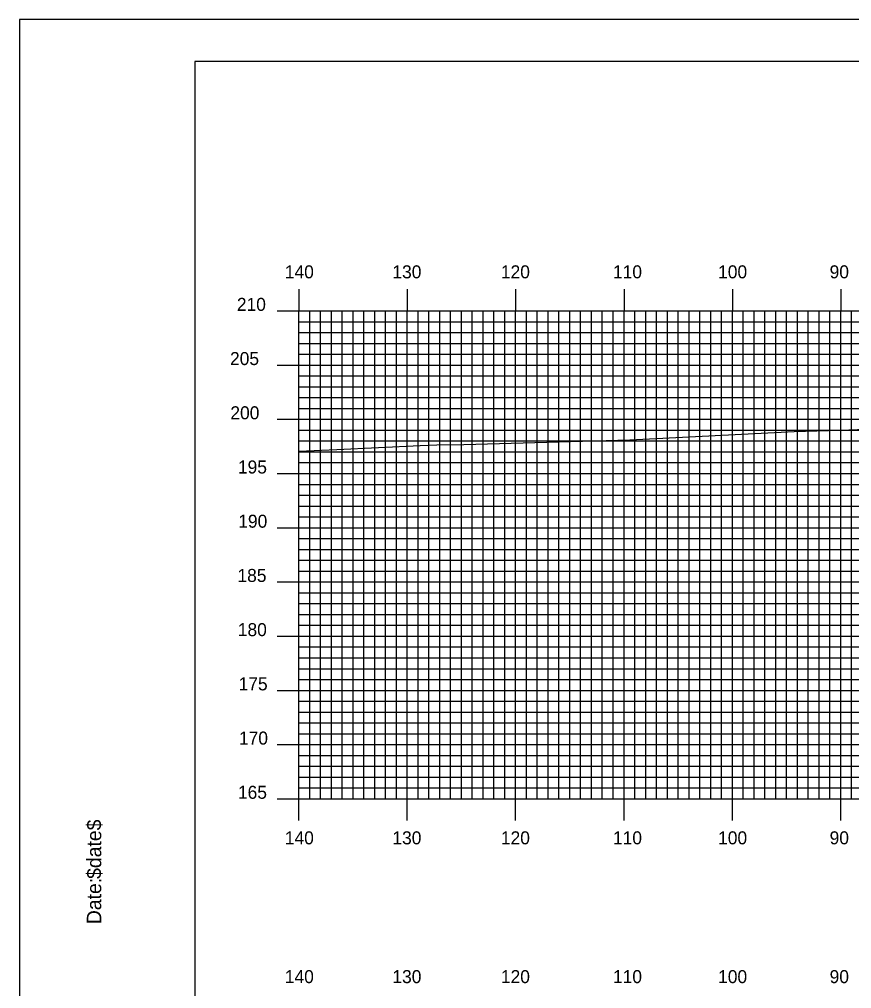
# Model space of a CAD drawing. Extents: x 1795633 to 1795976, y 442591 to 442811.
# Drawn here: x 1795633.1 to 1795709.9, y 442721.2 to 442810.5 of the extents above; entities that cross this region are included whole.
import ezdxf

# ---------------------------------------------------------------- set-up
doc = ezdxf.new("R2010")
doc.units = 0
for name, color, linetype in [('BORDER', 7, 'Continuous'), ('H_V ANNOTATION', 7, 'Continuous'), ('MAJOR', 7, 'Continuous'), ('MINOR', 7, 'Continuous'), ('PLOT BOUNDARY', 7, 'Continuous'), ('S_Roadway_Centerline', 7, 'Continuous')]:
    doc.layers.add(name, color=color, linetype=linetype)

msp = doc.modelspace()

# ---------------------------------------------------------------- linework, layer by layer
at = {"layer": 'BORDER'}
msp.add_lwpolyline([(1795649.279, 442596.665), (1795969.279, 442596.665), (1795969.279, 442806.665), (1795649.279, 442806.665)], close=True, dxfattribs=at)
at = {"layer": 'MAJOR'}
for p, q in [((1795658.879, 442785.669), (1795658.879, 442783.665)), ((1795668.879, 442785.669), (1795668.879, 442783.665)), ((1795678.879, 442785.669), (1795678.879, 442783.665)), ((1795688.879, 442785.669), (1795688.879, 442783.665)), ((1795698.879, 442785.669), (1795698.879, 442783.665)), ((1795708.879, 442785.669), (1795708.879, 442783.665)), ((1795656.875, 442783.665), (1795658.879, 442783.665)), ((1795658.879, 442783.665), (1795938.879, 442783.665)), ((1795658.879, 442738.665), (1795658.879, 442783.665)), ((1795658.879, 442738.665), (1795658.879, 442783.665)), ((1795658.879, 442783.665), (1795938.879, 442783.665)), ((1795668.879, 442738.665), (1795668.879, 442783.665)), ((1795678.879, 442738.665), (1795678.879, 442783.665)), ((1795688.879, 442738.665), (1795688.879, 442783.665)), ((1795698.879, 442738.665), (1795698.879, 442783.665)), ((1795708.879, 442738.665), (1795708.879, 442783.665)), ((1795656.875, 442778.665), (1795658.879, 442778.665)), ((1795658.879, 442778.665), (1795938.879, 442778.665)), ((1795656.875, 442773.665), (1795658.879, 442773.665)), ((1795658.879, 442773.665), (1795938.879, 442773.665)), ((1795656.875, 442768.665), (1795658.879, 442768.665)), ((1795658.879, 442768.665), (1795938.879, 442768.665)), ((1795656.875, 442763.665), (1795658.879, 442763.665)), ((1795658.879, 442763.665), (1795938.879, 442763.665)), ((1795656.875, 442758.665), (1795658.879, 442758.665)), ((1795658.879, 442758.665), (1795938.879, 442758.665)), ((1795656.875, 442753.665), (1795658.879, 442753.665)), ((1795658.879, 442753.665), (1795938.879, 442753.665)), ((1795656.875, 442748.665), (1795658.879, 442748.665)), ((1795658.879, 442748.665), (1795938.879, 442748.665)), ((1795656.875, 442743.665), (1795658.879, 442743.665)), ((1795658.879, 442743.665), (1795938.879, 442743.665)), ((1795656.875, 442738.665), (1795658.879, 442738.665)), ((1795658.879, 442738.665), (1795938.879, 442738.665)), ((1795658.879, 442738.665), (1795938.879, 442738.665)), ((1795658.879, 442736.661), (1795658.879, 442738.665)), ((1795668.879, 442736.661), (1795668.879, 442738.665)), ((1795678.879, 442736.661), (1795678.879, 442738.665)), ((1795688.879, 442736.661), (1795688.879, 442738.665)), ((1795698.879, 442736.661), (1795698.879, 442738.665)), ((1795708.879, 442736.661), (1795708.879, 442738.665))]:
    msp.add_line(p, q, dxfattribs=at)
at = {"layer": 'MINOR'}
for p, q in [((1795659.879, 442738.665), (1795659.879, 442783.665)), ((1795660.879, 442738.665), (1795660.879, 442783.665)), ((1795661.879, 442738.665), (1795661.879, 442783.665)), ((1795662.879, 442738.665), (1795662.879, 442783.665)), ((1795663.879, 442738.665), (1795663.879, 442783.665)), ((1795664.879, 442738.665), (1795664.879, 442783.665)), ((1795665.879, 442738.665), (1795665.879, 442783.665)), ((1795666.879, 442738.665), (1795666.879, 442783.665)), ((1795667.879, 442738.665), (1795667.879, 442783.665)), ((1795669.879, 442738.665), (1795669.879, 442783.665)), ((1795670.879, 442738.665), (1795670.879, 442783.665)), ((1795671.879, 442738.665), (1795671.879, 442783.665)), ((1795672.879, 442738.665), (1795672.879, 442783.665)), ((1795673.879, 442738.665), (1795673.879, 442783.665)), ((1795674.879, 442738.665), (1795674.879, 442783.665)), ((1795675.879, 442738.665), (1795675.879, 442783.665)), ((1795676.879, 442738.665), (1795676.879, 442783.665)), ((1795677.879, 442738.665), (1795677.879, 442783.665)), ((1795679.879, 442738.665), (1795679.879, 442783.665)), ((1795680.879, 442738.665), (1795680.879, 442783.665)), ((1795681.879, 442738.665), (1795681.879, 442783.665)), ((1795682.879, 442738.665), (1795682.879, 442783.665)), ((1795683.879, 442738.665), (1795683.879, 442783.665)), ((1795684.879, 442738.665), (1795684.879, 442783.665)), ((1795685.879, 442738.665), (1795685.879, 442783.665)), ((1795686.879, 442738.665), (1795686.879, 442783.665)), ((1795687.879, 442738.665), (1795687.879, 442783.665)), ((1795689.879, 442738.665), (1795689.879, 442783.665)), ((1795690.879, 442738.665), (1795690.879, 442783.665)), ((1795691.879, 442738.665), (1795691.879, 442783.665)), ((1795692.879, 442738.665), (1795692.879, 442783.665)), ((1795693.879, 442738.665), (1795693.879, 442783.665)), ((1795694.879, 442738.665), (1795694.879, 442783.665)), ((1795695.879, 442738.665), (1795695.879, 442783.665)), ((1795696.879, 442738.665), (1795696.879, 442783.665)), ((1795697.879, 442738.665), (1795697.879, 442783.665)), ((1795699.879, 442738.665), (1795699.879, 442783.665)), ((1795700.879, 442738.665), (1795700.879, 442783.665)), ((1795701.879, 442738.665), (1795701.879, 442783.665)), ((1795702.879, 442738.665), (1795702.879, 442783.665)), ((1795703.879, 442738.665), (1795703.879, 442783.665)), ((1795704.879, 442738.665), (1795704.879, 442783.665)), ((1795705.879, 442738.665), (1795705.879, 442783.665)), ((1795706.879, 442738.665), (1795706.879, 442783.665)), ((1795707.879, 442738.665), (1795707.879, 442783.665)), ((1795709.879, 442738.665), (1795709.879, 442783.665)), ((1795658.879, 442782.665), (1795938.879, 442782.665)), ((1795658.879, 442782.665), (1795660.883, 442782.665)), ((1795658.879, 442781.665), (1795938.879, 442781.665)), ((1795658.879, 442781.665), (1795660.883, 442781.665)), ((1795658.879, 442780.665), (1795938.879, 442780.665)), ((1795658.879, 442780.665), (1795660.883, 442780.665)), ((1795658.879, 442779.665), (1795938.879, 442779.665)), ((1795658.879, 442779.665), (1795660.883, 442779.665)), ((1795658.879, 442777.665), (1795938.879, 442777.665)), ((1795658.879, 442777.665), (1795660.883, 442777.665)), ((1795658.879, 442776.665), (1795938.879, 442776.665)), ((1795658.879, 442776.665), (1795660.883, 442776.665)), ((1795658.879, 442775.665), (1795938.879, 442775.665)), ((1795658.879, 442775.665), (1795660.883, 442775.665)), ((1795658.879, 442774.665), (1795938.879, 442774.665)), ((1795658.879, 442774.665), (1795660.883, 442774.665)), ((1795658.879, 442772.665), (1795938.879, 442772.665)), ((1795658.879, 442772.665), (1795660.883, 442772.665)), ((1795658.879, 442771.665), (1795938.879, 442771.665)), ((1795658.879, 442771.665), (1795660.883, 442771.665)), ((1795658.879, 442770.665), (1795938.879, 442770.665)), ((1795658.879, 442770.665), (1795660.883, 442770.665)), ((1795658.879, 442769.665), (1795938.879, 442769.665)), ((1795658.879, 442769.665), (1795660.883, 442769.665)), ((1795658.879, 442767.665), (1795938.879, 442767.665)), ((1795658.879, 442767.665), (1795660.883, 442767.665)), ((1795658.879, 442766.665), (1795938.879, 442766.665)), ((1795658.879, 442766.665), (1795660.883, 442766.665)), ((1795658.879, 442765.665), (1795938.879, 442765.665)), ((1795658.879, 442765.665), (1795660.883, 442765.665)), ((1795658.879, 442764.665), (1795938.879, 442764.665)), ((1795658.879, 442764.665), (1795660.883, 442764.665)), ((1795658.879, 442762.665), (1795938.879, 442762.665)), ((1795658.879, 442762.665), (1795660.883, 442762.665)), ((1795658.879, 442761.665), (1795938.879, 442761.665)), ((1795658.879, 442761.665), (1795660.883, 442761.665)), ((1795658.879, 442760.665), (1795938.879, 442760.665)), ((1795658.879, 442760.665), (1795660.883, 442760.665)), ((1795658.879, 442759.665), (1795938.879, 442759.665)), ((1795658.879, 442759.665), (1795660.883, 442759.665)), ((1795658.879, 442757.665), (1795938.879, 442757.665)), ((1795658.879, 442757.665), (1795660.883, 442757.665)), ((1795658.879, 442756.665), (1795938.879, 442756.665)), ((1795658.879, 442756.665), (1795660.883, 442756.665)), ((1795658.879, 442755.665), (1795938.879, 442755.665)), ((1795658.879, 442755.665), (1795660.883, 442755.665)), ((1795658.879, 442754.665), (1795938.879, 442754.665)), ((1795658.879, 442754.665), (1795660.883, 442754.665)), ((1795658.879, 442752.665), (1795834.579, 442752.665)), ((1795658.879, 442752.665), (1795660.883, 442752.665)), ((1795658.879, 442751.665), (1795938.879, 442751.665)), ((1795658.879, 442751.665), (1795660.883, 442751.665)), ((1795658.879, 442750.665), (1795938.879, 442750.665)), ((1795658.879, 442750.665), (1795660.883, 442750.665)), ((1795658.879, 442749.665), (1795938.879, 442749.665)), ((1795658.879, 442749.665), (1795660.883, 442749.665)), ((1795658.879, 442747.665), (1795938.879, 442747.665)), ((1795658.879, 442747.665), (1795660.883, 442747.665)), ((1795658.879, 442746.665), (1795938.879, 442746.665)), ((1795658.879, 442746.665), (1795660.883, 442746.665)), ((1795658.879, 442745.665), (1795938.879, 442745.665)), ((1795658.879, 442745.665), (1795660.883, 442745.665)), ((1795658.879, 442744.665), (1795938.879, 442744.665)), ((1795658.879, 442744.665), (1795660.883, 442744.665)), ((1795658.879, 442742.665), (1795938.879, 442742.665)), ((1795658.879, 442742.665), (1795660.883, 442742.665)), ((1795658.879, 442741.665), (1795938.879, 442741.665)), ((1795658.879, 442741.665), (1795660.883, 442741.665)), ((1795658.879, 442740.665), (1795938.879, 442740.665)), ((1795658.879, 442740.665), (1795660.883, 442740.665)), ((1795658.879, 442739.665), (1795938.879, 442739.665)), ((1795658.879, 442739.665), (1795660.883, 442739.665))]:
    msp.add_line(p, q, dxfattribs=at)
at = {"layer": 'PLOT BOUNDARY'}
msp.add_lwpolyline([(1795633.092, 442590.547), (1795973.092, 442590.547), (1795973.092, 442810.547), (1795633.092, 442810.547)], close=True, dxfattribs=at)
at = {"layer": 'S_Roadway_Centerline'}
msp.add_lwpolyline([(1795658.879, 442770.74), (1795662.388, 442770.885), (1795670.086, 442771.237), (1795671.614, 442771.301), (1795674.092, 442771.331), (1795689.424, 442771.778), (1795704.576, 442772.528), (1795708.794, 442772.673), (1795718.563, 442773.044)], dxfattribs=at)

# ---------------------------------------------------------------- texts
at = {"layer": 'BORDER'}
for s, p in [('$date$', (1795640.649, 442731.275)), ('Date:', (1795640.649, 442727.099))]:
    msp.add_text(s, height=1.3392, rotation=90, dxfattribs=at).set_placement(p)
at = {"layer": 'H_V ANNOTATION'}
for s, p in [('140', (1795657.584, 442786.665)), ('130', (1795667.509, 442786.665)), ('120', (1795677.52, 442786.665)), ('110', (1795687.862, 442786.665)), ('100', (1795697.562, 442786.665)), ('90', (1795707.851, 442786.665)), ('210', (1795653.16, 442783.665)), ('205', (1795652.528, 442778.665)), ('200', (1795652.56, 442773.665)), ('195', (1795653.257, 442768.665)), ('190', (1795653.289, 442763.665)), ('185', (1795653.214, 442758.665)), ('180', (1795653.246, 442753.665)), ('175', (1795653.321, 442748.665)), ('170', (1795653.353, 442743.665)), ('165', (1795653.257, 442738.665)), ('140', (1795657.584, 442734.465)), ('130', (1795667.509, 442734.465)), ('120', (1795677.52, 442734.465)), ('110', (1795687.862, 442734.465)), ('100', (1795697.562, 442734.465)), ('90', (1795707.851, 442734.465)), ('140', (1795657.584, 442721.665)), ('130', (1795667.509, 442721.665)), ('120', (1795677.52, 442721.665)), ('110', (1795687.862, 442721.665)), ('100', (1795697.562, 442721.665)), ('90', (1795707.851, 442721.665))]:
    msp.add_text(s, height=1.2, dxfattribs=at).set_placement(p)
at = {"layer": 'MAJOR'}
msp.add_text('-', height=0.012, dxfattribs=at).set_placement((1795658.87, 442738.665))

doc.saveas('drawing.dxf')
